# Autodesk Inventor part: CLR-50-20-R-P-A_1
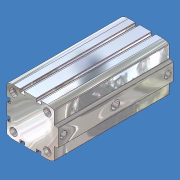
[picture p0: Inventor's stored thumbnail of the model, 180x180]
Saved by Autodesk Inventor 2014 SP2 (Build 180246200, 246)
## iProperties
Shininess: 64.0
Length Units: 11269
Angle Units: 11279
Time Units: 11290
Mass Units: 11283
Length Display Precision: 3
Angle Display Precision: 2
Compacted: True
Part Number: CLR-50-20-R-P-A_1
Document SubType Name: Modeling
Created: 2004-03
Material: Allgemein
Cost Center: 0,4 kg
Designer: Peter Kastler
Manufacturer: Standard
Standards Organization: Custom
Density: 1 g/cm^3
Appearance: Metall - Alu(glänzend)
Density: 0.0
Volumn: 0.0
Area: 0.0
PropertySet Name: Model Information
Control State: 0
Master: False
Checked Out: False
Übersetzungsnorm: STEP AP203
Dateiname: 535459_CLR_50_20_R_P_A.stp
Postprozessor: Build: 081d, Release: 8 SP1 - Date: Tue 01/26/2004
Gesendete Einheiten: MILLIMETERS
Unbestimmtheit: 1e-06
TotalMass: 0,4 kg
Cideon_Mass: 0.4
Cideon_Mass_Unit: kg
Cideon_Area: 0,101 m^2
Cideon_User: konstruktion
Cideon_SaveDate: 10.10.2018
Cideon_SaveTime: 09:12:01
Author: Peter Kastler
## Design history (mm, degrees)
feature "Basis1"
node "Volumenkörper1"
node "Volumenkörper"
node "Flächenkörper"
